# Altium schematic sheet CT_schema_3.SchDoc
size 357 x 214 mm
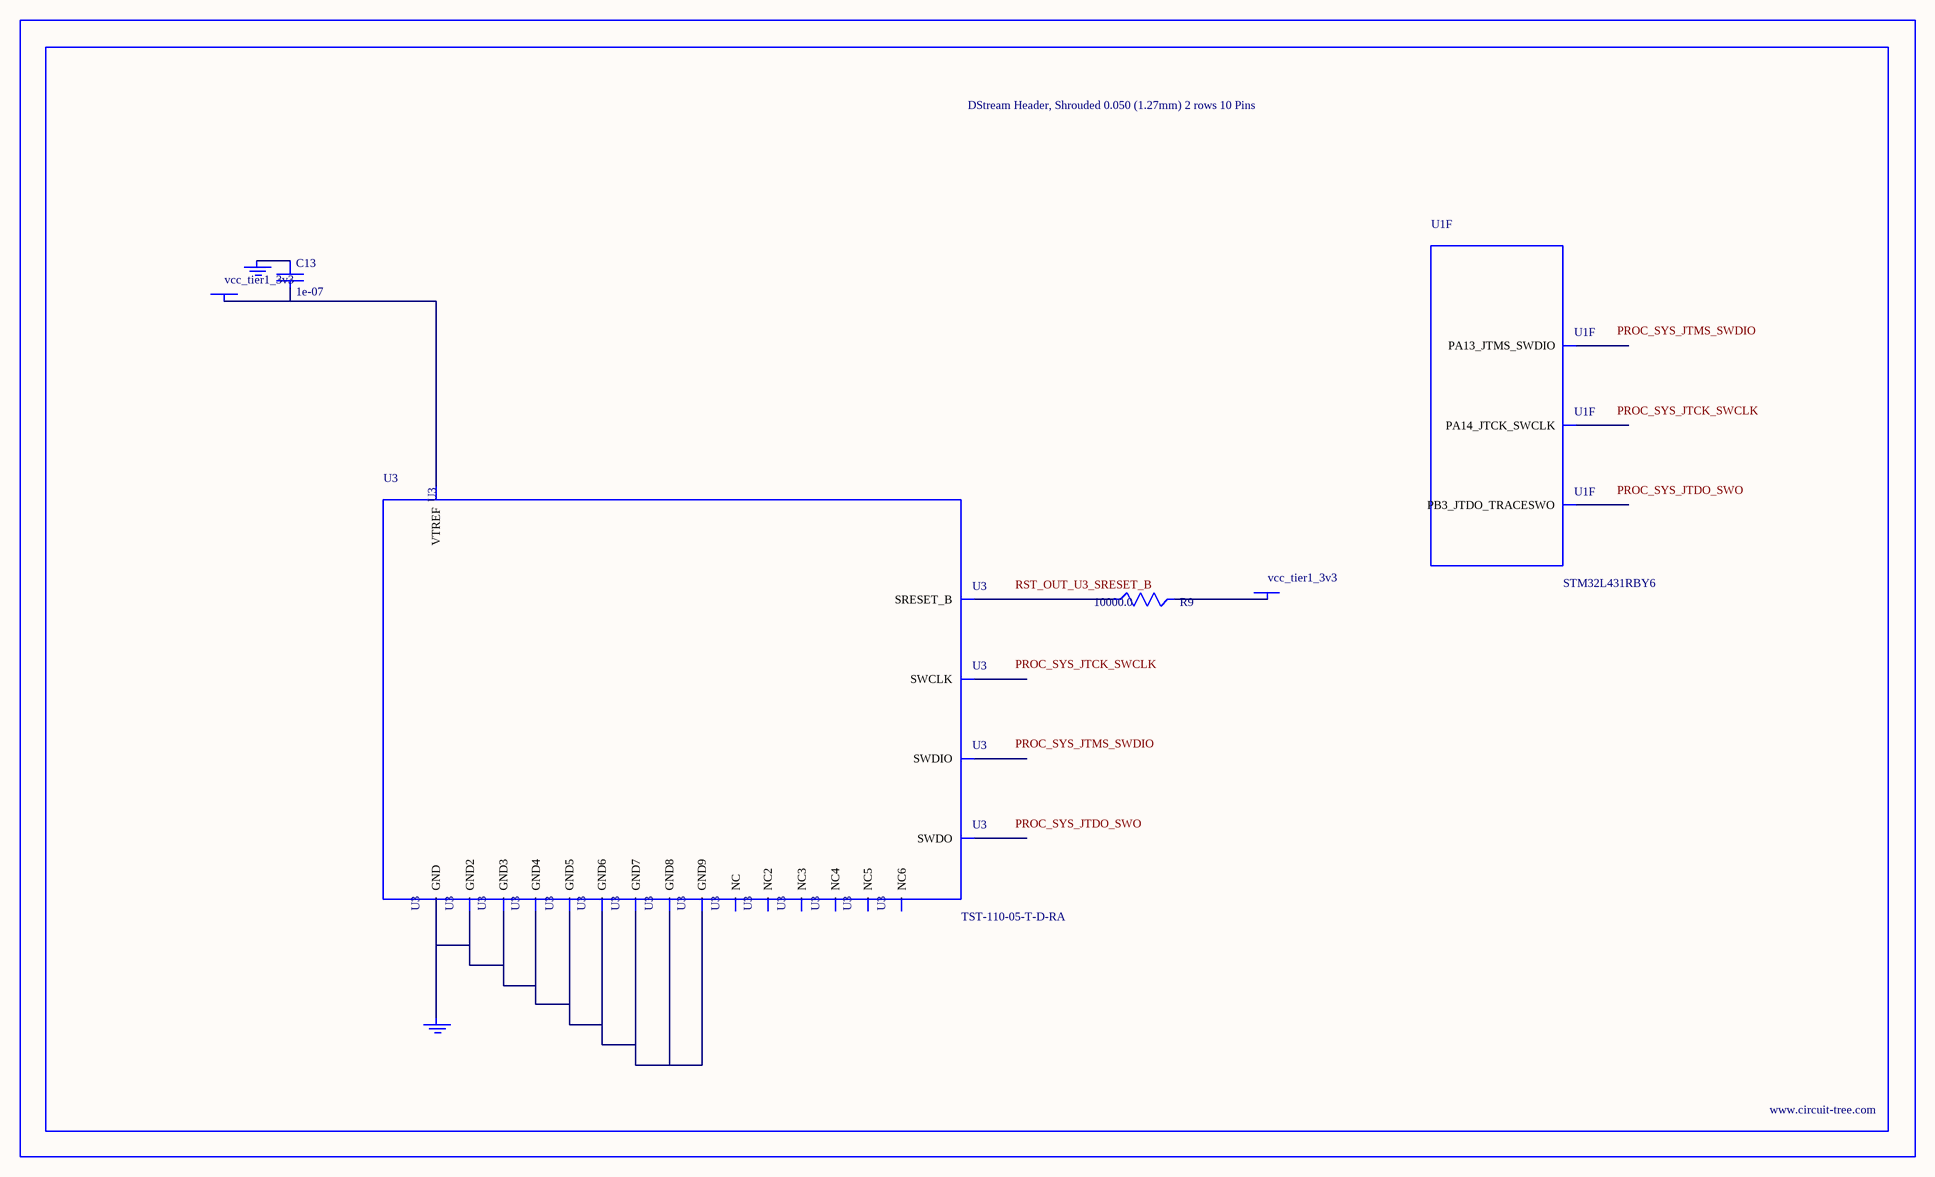
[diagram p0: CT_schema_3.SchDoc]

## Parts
BORDER2  (no value)
C13  1e-07  [C0402]
GND_INSTANCE_2_0  (no value)
GND_INSTANCE_2_1  (no value)
POWER_INSTANCE_2_0  vcc_tier1_3v3
POWER_INSTANCE_2_1  vcc_tier1_3v3
R9  10000.0  [R0603]
U1  STM32L431RBY6  [WLCSP64]  (part F of 7)
U3  TST-110-05-T-D-RA  [TST-110-05-T-D-RA]

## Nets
NetC13_1: C13.1 GND_INSTANCE_2_0.0(GND)
NetC13_2: C13.2 POWER_INSTANCE_2_0.0(PWR) U3.1(VTREF)
NetGND_INSTANCE_2_1_0: GND_INSTANCE_2_1.0(GND) U3.4(GND) U3.6(GND2) U3.8(GND3) U3.10(GND4) U3.12(GND5) U3.14(GND6) U3.16(GND7) U3.18(GND8) U3.20(GND9)
NetPOWER_INSTANCE_2_1_0: POWER_INSTANCE_2_1.0(PWR) R9.2
NetR9_1: R9.1 U3.15(SRESET_B)

Not connected (* = marked no-connect by the designer): U1 A5(PB3_JTDO_TRACESWO) B2(PA14_JTCK_SWCLK) C2(PA13_JTMS_SWDIO); U3 2(NC) 3(NC2) 5(NC3) 7(SWDIO) 9(SWCLK) 11(NC4) 13(SWDO) 17(NC5) 19(NC6)

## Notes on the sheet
- Labels drawn without touching a wire or pin: PROC_SYS_JTCK_SWCLK, PROC_SYS_JTDO_SWO, PROC_SYS_JTMS_SWDIO, RST_OUT_U3_SRESET_B

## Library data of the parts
BORDER2 = BORDER_PAGE2
C13 = C0402C104K3RACTU
GND_INSTANCE_2_0 GND_INSTANCE_2_1 = GND
POWER_INSTANCE_2_0 POWER_INSTANCE_2_1 = PWR
R9 = RC0603JR-0710KL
